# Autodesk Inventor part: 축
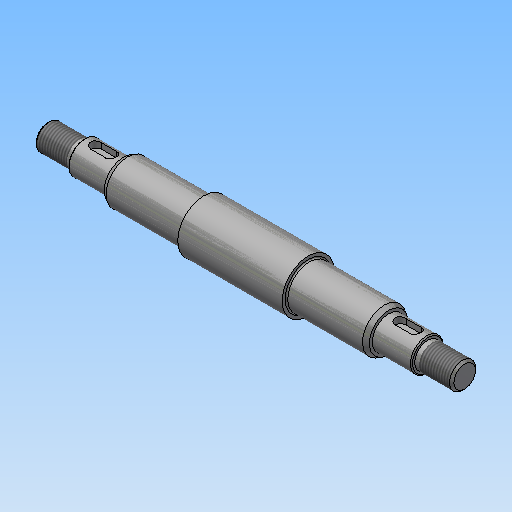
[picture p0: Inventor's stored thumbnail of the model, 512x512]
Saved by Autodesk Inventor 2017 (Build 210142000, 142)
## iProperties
Created: 2018-11
Part Number: 축
Material: 강철, 연강
Document SubType Name: Modeling
Designer: mduedu
Density: 1 g/cm^3
Appearance: 강철
Author: mduedu
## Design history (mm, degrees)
sketch "스케치1"
  geometry: L1 (-24, 0)-(24, 0); L2 (24, 0)-(24, 12); L3 (24, 12)-(-24, 12); L4 (-24, 12)-(-24, 0); L5 (-24, 0)-(-79, 0); L6 (-79, 0)-(-79, 7.5); L7 (-79, 7.5)-(-61, 7.5); L8 (-24, 7.5)-(-24, 0); L9 (-79, 0)-(-96, 0); L10 (-96, 0)-(-96, 6); L11 (-96, 6)-(-79, 6); L12 (-79, 6)-(-79, 0); L13 (0, 0)-(0, 12); L14 (24, 0)-(79, 0); L15 (79, 0)-(79, 7.5); L16 (79, 7.5)-(61, 7.5); L17 (24, 7.5)-(24, 0); L18 (79, 0)-(96, 0); L19 (96, 0)-(96, 6); L20 (96, 6)-(79, 6); L21 (79, 6)-(79, 0); L22 (-61, 7.5)-(-61, 8.85); L23 (-59.008, 10)-(-24, 10); L24 (24, 10)-(59.008, 10); L25 (61, 8.85)-(61, 7.5); L26 (-61, 8.85)-(-59.008, 10); L27 (61, 8.85)-(59.008, 10); 1 further point
  constraints: 54 end point, 9 parallel, 6 symmetric about line, 4 horizontal, 4 perpendicular, 2 midpoint, 2 point on line, 1 coincident
  dimensions: "d0" = 24 diameter of L3 L1; "d2" = 15 diameter of L7 L5; "d3" = 12 diameter of L11 L9; "d4" = 48 distance of L2.end L3.end; "d5" = 55 distance of L6.end L8.start; "d6" = 192 distance between parallel lines of L19 L10; "d24" = 20 diameter of L23 L5; "d25" = 18 distance of L6.end L7.end; "d26" = 18 distance of L15.end L16.end; "d27" = 20 diameter of L24 L14; "d28" = 55 distance between parallel lines of L15 L2; "d29" = 30 deg angle of L23 L26; "d30" = 17.7 diameter of L22.end L5; "d31" = 30 deg angle of L24 L27; "d32" = 17.7 diameter of L25.start L14
revolve "회전1" sketch "스케치1" stored, may be unused: angle "d7" = 90 deg
fillet "모깎기1" dims "d8" = 0.6
node "작업 평면1"
sketch "스케치2" dims "d11" = 12
  geometry: L1 (-3.5, 2.5)-(3.5, 2.5); L2 (3.5, 2.5)-(3.5, -2.5); L3 (3.5, -2.5)-(-3.5, -2.5); L4 (-3.5, -2.5)-(-3.5, 2.5); L5 (9, 7.5)-(9, -7.5) reference; 3 further points
  constraints: 8 end point, 2 midpoint, 2 parallel, 2 vertical alignment, 1 horizontal, 1 horizontal alignment, 1 perpendicular, 4 other
  dimensions: "d9" = 3 dimension on L5; "d10" = 5 distance between parallel lines of L3 L1
extrude "돌출1" cut sketch "스케치2" distance "d12" = 3; taper "d13" = 0 deg
chamfer "모따기1" distance "d14" = 0.5; stored, may be unused: second distance "d15" = 2, angle "d16" = 45 deg
feature "스레드1" dims "d17" = 15, "d18" = 0
feature "스레드2" dims "d19" = 15, "d20" = 0
chamfer "모따기2" distance "d21" = 1; stored, may be unused: second distance "d22" = 2, angle "d23" = 45 deg
node "솔리드1"
mirror "대칭1"
